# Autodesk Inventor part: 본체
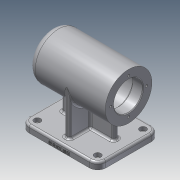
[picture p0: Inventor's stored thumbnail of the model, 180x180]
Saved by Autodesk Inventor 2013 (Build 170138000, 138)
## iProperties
Created: 2020-10
Part Number: 본체
Material: 알루미늄 6061
Document SubType Name: Modeling
Designer: 19
Density: 1 g/cm^3
Author: 19
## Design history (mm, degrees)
sketch "스케치1"
  geometry: C1 r 34 at (0, 0); 1 further point
  constraints: 1 centre point, 1 coincident
  dimensions: "d0" = 68 diameter of C1
extrude "돌출1" new body sketch "스케치1" stored distance "d1" = 112; taper "d2" = 0 deg
sketch "스케치2"
  geometry: L1 (34, -56)-(-34, -56) reference; L2 (-34, -56)-(-34, 56) reference; L3 (-34, 56)-(34, 56) reference; L4 (34, 56)-(34, -56) reference; L5 (0, 56)-(0, -56); L6 (0, 50)-(10.5, 50); L7 (10.5, 50)-(10.5, 47); L8 (10.5, 47)-(16, 47); L9 (16, 47)-(16, 43); L10 (16, 43)-(17.5, 43); L11 (17.5, 43)-(17.5, 25); L12 (17.5, 25)-(21, 25); L13 (21, 25)-(21, 13); L14 (21, 13)-(24, 13); L15 (24, 13)-(24, -41); L16 (24, -41)-(21, -41); L17 (21, -41)-(21, -56); L18 (0, -56)-(21, -56); 1 further point
  constraints: 28 end point, 8 parallel, 5 perpendicular, 2 midpoint, 2 point on line
  dimensions: "d20" = 42 diameter of L17 L5; "d22" = 15 distance between parallel lines of L16 L1; "d23" = 48 diameter of L15 L5; "d24" = 54 distance between parallel lines of L14 L16; "d25" = 42 diameter of L13 L5; "d26" = 12 distance between parallel lines of L14 L12; "d28" = 35 diameter of L11 L5; "d29" = 18 distance between parallel lines of L12 L10; "d30" = 32 diameter of L9 L5; "d31" = 4 distance between parallel lines of L10 L8; "d32" = 21 diameter of L7 L5; "d33" = 3 distance between parallel lines of L8 L6
revolve "회전1" sketch "스케치2" stored, may be unused: angle "d34" = 90 deg
node "작업 평면1"
sketch "스케치3"
  geometry: L1 (-34, -56)-(34, -56) reference; L2 (33, 56)-(-33, 56); L3 (-45, 44)-(-45, -44); L4 (-33, -56)-(33, -56); L5 (45, -44)-(45, 44); L6 (45, 56)-(-45, -56); L7 (-45, 56)-(45, -56); A1 r 12 centre (33, 44) between (45, 44) and (33, 56); A2 r 12 centre (33, -44) between (33, -56) and (45, -44); A3 r 12 centre (-33, -44) between (-45, -44) and (-33, -56); A4 r 12 centre (-33, 44) between (-33, 56) and (-45, 44); 3 further points
  constraints: 12 end point, 8 point on circle, 8 point on line, 8 tangent, 4 centre point, 4 midpoint, 3 equal radius, 2 parallel, 1 horizontal, 1 perpendicular
  dimensions: "d36" = 90 distance of L7.end L6.end; "d37" = 112 distance of L6.end L7.start; "d38" = 12 radius of A1
extrude "돌출2" join sketch "스케치3" distance "d39" = 10; taper "d40" = 0 deg
sketch "스케치4"
  geometry: L1 (34, -4)-(-34, -4); L2 (-34, -4)-(-34, 4); L3 (-34, 4)-(34, 4); L4 (34, 4)-(34, -4); L5 (34, -4)-(-34, 4); L6 (-34, -4)-(34, 4); 1 further point
  constraints: 12 end point, 2 midpoint, 2 parallel, 1 horizontal, 1 perpendicular
  dimensions: "d45" = 68 distance of L2.end L3.end; "d46" = 8 distance of L1.end L2.end
extrude "돌출3" join sketch "스케치4" stored distance "d47" = 10; taper "d48" = 0 deg
sketch "스케치6"
  geometry: L1 (33, 56)-(-33, 56) reference; L2 (-4, -38)-(4, -38); L3 (4, -38)-(4, 38); L4 (4, 38)-(-4, 38); L5 (-4, 38)-(-4, -38); L6 (-4, -38)-(4, 38); L7 (4, -38)-(-4, 38); 1 further point
  constraints: 12 end point, 2 midpoint, 2 parallel, 1 horizontal, 1 perpendicular
  dimensions: "d73" = 18 distance between parallel lines of L4 L1; "d74" = 8 distance between parallel lines of L3 L5
extrude "돌출5" join sketch "스케치6" stored distance "d56" = 10; taper "d57" = 0 deg
sketch "스케치7"
  geometry: L1 (88, 0)-(0, 0) reference; L2 (100, 0)-(100, 10) reference; 2 further points
  constraints: 1 other
  dimensions: "d58" = 3 distance from line of L1 point (44, 3); "d59" = 56 distance from line of L2 point (44, 3)
feature "엠보싱1" sketch "스케치7" dims "d60" = 0.5, "d61" = 0
sketch "스케치8" dims "d62" = 52
  geometry: C1 r 21 at (0, 0) reference; C2 r 34 at (0, 0) reference; 2 further points
  constraints: 2 vertical alignment, 1 coincident, 2 other
hole "구멍1" sketch "스케치8" at (0, 26) diameter "d63" = 3.242; stored, may be unused: countersink angle "d67" = 90 deg, drill point angle "d69" = 118 deg; dims "d64" = 8, "d65" = 4, "d66" = 2, "d68" = 11
sketch "스케치9"
  geometry: 1 further point
fillet "모깎기1" dims "d75" = 3
fillet "모깎기2" dims "d76" = 0.3
chamfer "모따기1" distance "d77" = 1; stored, may be unused: second distance "d78" = 2, angle "d79" = 45 deg
fillet "모깎기3" dims "d80" = 10
sketch "스케치10"
  geometry: C1 r 4.75 at (-33, 44); C2 r 4.75 at (33, 44); C3 r 4.75 at (-33, -44); C4 r 4.75 at (33, -44); A1 r 12 centre (-33, -44) between (-45, -44) and (-33, -56) reference; A2 r 12 centre (33, -44) between (33, -56) and (45, -44) reference; A3 r 12 centre (33, 44) between (45, 44) and (33, 56) reference; A4 r 12 centre (-33, 44) between (-33, 56) and (-45, 44) reference; 1 further point
  constraints: 4 centre point, 4 coincident
  dimensions: "d81" = 9.5 diameter of C1; "d82" = 9.5 diameter of C2; "d83" = 9.5 diameter of C3; "d84" = 9.5 diameter of C4
extrude "돌출6" cut sketch "스케치10" distance "d85" = 5.4; taper "d86" = 0 deg
sketch "스케치11"
  geometry: C1 r 2.75 at (33, 44); C2 r 2.75 at (33, -44); C3 r 2.75 at (-33, 44); C4 r 2.75 at (-33, -44); A1 r 12 centre (-33, -44) between (-45, -44) and (-33, -56) reference; A2 r 12 centre (33, -44) between (33, -56) and (45, -44) reference; A3 r 12 centre (33, 44) between (45, 44) and (33, 56) reference; A4 r 12 centre (-33, 44) between (-33, 56) and (-45, 44) reference; 1 further point
  constraints: 4 centre point, 4 coincident
  dimensions: "d87" = 5.5 diameter of C1; "d88" = 5.5 diameter of C2; "d89" = 5.5 diameter of C3; "d90" = 5.5 diameter of C4
extrude "돌출7" cut sketch "스케치11" distance "d91" = 10; taper "d92" = 0 deg
fillet "모깎기4" dims "d93" = 3
fillet "모깎기5" dims "d94" = 3
fillet "모깎기6" dims "d95" = 3
fillet "모깎기7" dims "d96" = 3
node "솔리드1"
pattern_circular "원형 패턴1" dims angle "d71" = 360 deg
node "절단 모서리 투영1"
other parameters: "d35" = -74
